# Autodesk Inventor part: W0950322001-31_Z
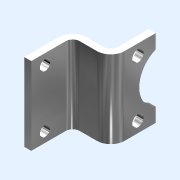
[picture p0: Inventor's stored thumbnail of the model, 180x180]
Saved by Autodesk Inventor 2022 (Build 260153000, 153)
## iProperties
Category: PARTsolutions
Company: METALWORK
Part Number: W0950322001-31_Z
Material: Generico
Catalog Web Link: www.cadenas.de
Description: FOOT - MODEL A_-
Vendor: METALWORK
Document SubType Name: Modeling
Designer: partserver
Manufacturer: METALWORK
Mass: 8.43033 g
Surface Area: 53.8353 cm^2
Volume: 8.43033 cm^3
Density: 1 g/cm^3
Appearance: Alluminio - Piatto
PSOL_IDENT_0: {$CADENAS_DATA\23d-libs\metalwork\actuators\parts\foot.prj},176 {VTYP=3D},{NB=W0950322001-31_},{LINA=
PSOL_IDENT_1: W0950322001},{NN=FOOT - MODEL A_},{DATE=18.06.2021 08:06:10},{GEOMDATE=02.08.2018 11:04:45},{VERSION=
PSOL_IDENT_2: },{LINEID=640},{WBVAR=},{WBNUMERIC=}  {NB=W0950322001-31_},{LINA=W0950322001},{KT=DUMMY},{IDNR=},{CO
PSOL_IDENT_3: DE=W0950322001},{VER=31},{V1=3},{DI=32},{A=45},{B=35.0},{C=32},{D=24.000},{XS=0.000},{AB=0.000},{AH=
PSOL_IDENT_4: 0.000},{AO=0.000},{AT=0.000},{AU=0.000},{NH=0.000},{TR=0.000},{US=0.000},{R=0.000},{E=7.0},{XA=0.000
PSOL_IDENT_5: },{SA=0.000},{H=32.0},{N=74.5},{N1=92.5},{S=4},{WG=76},{R1=15.500},{BH=26.000},{ND=6.000},{TG=32.500
PSOL_IDENT_6: },{DH=6.600},{SL=16.000},{UH=0.000},{H1=0.000},{H2=0.000}
NB: W0950322001-31_
NN: FOOT - MODEL A_
NBSYN: $CODE.-$VER._
LINA: W0950322001
CATALOG: Metalwork
CODE: W0950322001
VER: 31
V1: 3
DI: 32
A: 45
B: 35
C: 32
D: 24
XS: 0
AB: 0
AH: 0
AO: 0
AT: 0
AU: 0
NH: 0
TR: 0
US: 0
R: 0
E: 7
XA: 0
SA: 0
H: 32
N: 74.5
N1: 92.5
S: 4
WG: 76
R1: 15.5
BH: 26
ND: 6
TG: 32.5
DH: 6.6
SL: 16
UH: 0
H1: 0
H2: 0
SUPPLIER: METALWORK
ARTICLENO: W0950322001-31_
BOMINFO: W0950322001
CREATOR: CADENAS GmbH
Title: W0950322001
Author: Cadenas PARTsolutions
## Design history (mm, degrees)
sketch "Sketch_1"
  geometry: L1 (8, -32)-(18, -32); L2 (18, -32)-(18, -28); L3 (18, -28)-(8, -28); L4 (4, -24)-(4, -6); L5 (4, -6)-(0, -6); L6 (0, -6)-(0, -24); A1 r 8 centre (8, -24) between (0, -24) and (8, -32); A2 r 4 centre (8, -24) between (4, -24) and (8, -28)
  constraints: 12 end point, 4 point on circle, 2 centre point
  dimensions: "d37" = 4 distance of L4.end L5.end; "d38" = 18 distance of L5.end L6.end; "d39" = 4 distance of L1.end L2.end; "d40" = 8 radius of A1; "d41" = 4 radius of A2; "d43" = 18 distance between parallel lines of L6 L2
extrude "Extrusion1" join sketch "Sketch_1" stored distance "d0" = 45; taper "d1" = 0 deg
sketch "Sketch_2"
  geometry: C1 r 15.5 at (0, 0); 1 further point
  constraints: 1 centre point
extrude "Extrusion2" cut sketch "Sketch_2" distance "d2" = 4; taper "d3" = 0 deg
sketch "Sketch_3"
  geometry: C1 r 3.5 at (-24, -16); 1 further point
  constraints: 1 centre point
extrude "Extrusion3" cut sketch "Sketch_3" distance "d4" = 32; taper "d5" = 0 deg
sketch "Sketch_4"
  geometry: C1 r 3.5 at (-24, 16); 1 further point
  constraints: 1 centre point
extrude "Extrusion4" cut sketch "Sketch_4" distance "d6" = 32; taper "d7" = 0 deg
sketch "Sketch5"
  geometry: 1 further point
hole "Hole1" sketch "Sketch5" at (6.25, 7.75) diameter "d8" = 6.6; stored, may be unused: countersink angle "d12" = 90 deg, drill point angle "d14" = 0 deg; dims "d9" = 6, "d10" = 4, "d11" = 2, "d13" = 4
sketch "Sketch6"
  geometry: 1 further point
hole "Hole2" sketch "Sketch6" at (38.75, 7.75) diameter "d15" = 6.6; stored, may be unused: countersink angle "d19" = 90 deg, drill point angle "d21" = 0 deg; dims "d16" = 6, "d17" = 4, "d18" = 2, "d20" = 4
node "body_XY"
node "body_YZ"
node "body_ZX"
node "body_X"
node "body_Y"
node "body_Z"
node "body_Center"
node "screws_1_XY"
node "screws_1_YZ"
node "screws_1_ZX"
node "screws_1_X"
node "screws_1_Y"
node "screws_1_Z"
node "screws_1_Center"
node "screws_2_XY"
node "screws_2_YZ"
node "screws_2_ZX"
node "screws_2_X"
node "screws_2_Y"
node "screws_2_Z"
node "screws_2_Center"
sketch "Schizzo7"
  geometry: L1 (-8, -32)-(-18, -32) reference; L2 (-18, -32)-(-18, -37.56); L3 (-26, -36)-(-26, -56); L4 (-26, -56)-(-22, -56); L5 (-22, -56)-(-22, -36); L6 (-18, -28)-(-18, -32) reference; L7 (-18, -32)-(-18, -28); A1 r 4 centre (-18, -36) between (-18, -32) and (-22, -36); A2 r 8 centre (-18, -36) between (-18, -28) and (-26, -36); 1 further point
  constraints: 10 end point, 5 point on circle, 3 point on line, 2 centre point, 2 tangent, 2 vertical, 1 collinear, 1 horizontal
  dimensions: "d25" = 8 diameter of A1; "d26" = 16 diameter of A2; "d27" = 20 distance of L3.start L3.end; "d28" = 4 distance of L3.end L4.end
extrude "Estrusione5" join sketch "Schizzo7" stored distance "d29" = 10; taper "d30" = 0 deg
sketch "Schizzo8"
  geometry: L1 (-45, 20)-(-45, 0) reference; L2 (0, 0)-(-45, 0) reference; C1 r 3 at (-39, 8); 1 further point
  constraints: 1 centre point
  dimensions: "d31" = 6 diameter of C1; "d32" = 6 distance from line of L1 C1.centre; "d33" = 8 distance from line of L2 C1.centre
extrude "Estrusione6" cut sketch "Schizzo8" extent not by distance; stored distance "d34" = 0; taper "d35" = 0 deg
mirror "Specchio1"
body "Solid1"
other parameters: "d22" = 0, "d23" = 0, "d24" = 0
